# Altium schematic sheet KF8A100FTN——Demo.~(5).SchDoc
size A4
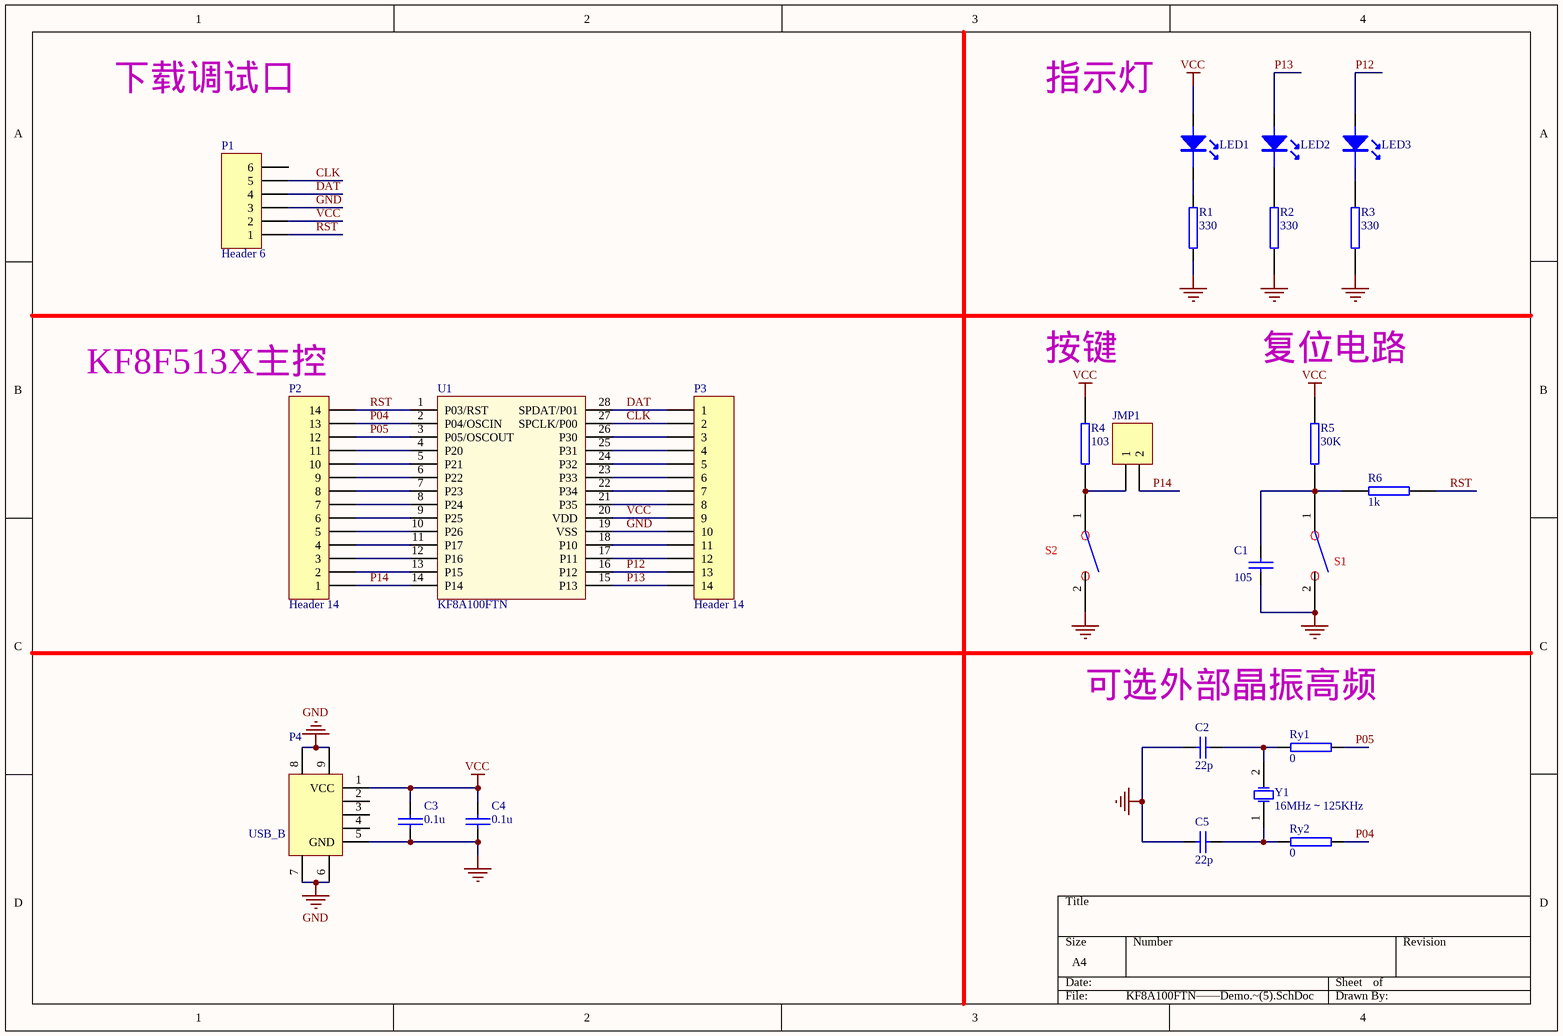
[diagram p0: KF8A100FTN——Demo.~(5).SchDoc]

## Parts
C1  105  [0603C]
C2  22p  [0603C]
C3  0.1u  [0603]
C4  0.1u  [0603]
C5  22p  [0603C]
JMP1  Header 2  [HDR1X2]  (value not drawn)
LED1  LED  [D0805]  (value not drawn)
LED2  LED  [D0805]  (value not drawn)
LED3  LED  [D0805]  (value not drawn)
P1  Header 6  [HDR1X6]
P2  Header 14  [HDR1X14]
P3  Header 14  [HDR1X14]
P4  USB_B
R1  330  [0603]
R2  330  [0603]
R3  330  [0603]
R4  103  [0603]
R5  30K  [0603]
R6  1k  [0603]
RESET1  (no value)  [KEY6*6]
Ry1  0  [0603]
Ry2  0  [0603]
SWITCH1  (no value)  [KEY6*6]
U1  KF8A100FTN
Y1  16MHz～125KHz  [CRYSTAL]

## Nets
GND: C1.2 C2.1 C3.2 C4.2 C5.1 P1.3 P3.10 P4.5(GND) P4.6 P4.7 R1.1 R2.1 R3.1 RESET1.2 SWITCH1.2 U1.19(VSS)
VCC: C3.1 C4.1 LED1.1 P1.2 P3.9 P4.1(VCC) R4.2 R5.2 U1.20(VDD)
CLK: P1.5 P3.2 U1.27(SPCLK/P00)
DAT: P1.4 P3.1 U1.28(SPDAT/P01)
P04: P2.13 Ry2.2 U1.2(P04/OSCIN)
P05: P2.12 Ry1.2 U1.3(P05/OSCOUT)
P12: LED3.1 P3.13 U1.16(P12)
P13: LED2.1 P3.14 U1.15(P13)
P14: JMP1.2 P2.1 U1.14(P14)
RST: P1.1 P2.14 R6.1 U1.1(P03/RST)
NetC1_1: C1.1 R5.1 R6.2 RESET1.1
NetC2_2: C2.2 Ry1.1 Y1.2(OSC2)
NetC5_2: C5.2 Ry2.1 Y1.1(OSC1)
NetJMP1_1: JMP1.1 R4.1 SWITCH1.1
NetLED1_2: LED1.2 R1.2
NetLED2_2: LED2.2 R2.2
NetP2_2: P2.2 U1.13(P15)
NetP2_3: P2.3 U1.12(P16)
NetP2_4: P2.4 U1.11(P17)
NetP2_5: P2.5 U1.10(P26)
NetP2_6: P2.6 U1.9(P25)
NetP2_7: P2.7 U1.8(P24)
NetP2_8: P2.8 U1.7(P23)
NetP2_9: P2.9 U1.6(P22)
NetP2_10: P2.10 U1.5(P21)
NetP2_11: P2.11 U1.4(P20)
NetP3_3: P3.3 U1.26(P30)
NetP3_4: P3.4 U1.25(P31)
NetP3_5: P3.5 U1.24(P32)
NetP3_6: P3.6 U1.23(P33)
NetP3_7: P3.7 U1.22(P34)
NetP3_8: P3.8 U1.21(P35)
NetP3_11: P3.11 U1.18(P10)
NetP3_12: P3.12 U1.17(P11)

Not connected (* = marked no-connect by the designer): P1 6; P4 2(VCC) 3(VCC) 4(VCC) 8 9; R3 2

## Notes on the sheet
- 下载调试口
- 指示灯
- KF8F513X主控
- 按键
- 复位电路
- (near SWITCH1) S2
- (near RESET1) S1
- (near C2) 可选外部晶振高频

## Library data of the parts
C1 C3 C4 = CAP: Capacitor
C2 C5 = Cap: Capacitor; Value: 30pF
JMP1 = Header 2: Header, 2-Pin
P1 = Header 6: Header, 6-Pin
P2 P3 = Header 14: Header, 14-Pin
R1-R6 Ry1 Ry2 = RES2
RESET1 SWITCH1 = KEY_X
Y1 = XTAL: Crystal Oscillator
